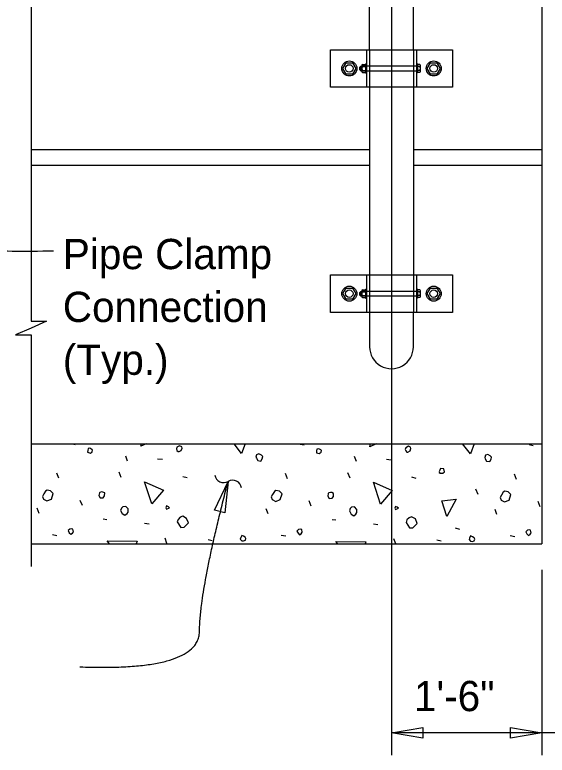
# Model space of a CAD drawing. Extents: x 0 to 41.1, y 0 to 26.4.
# Drawn here: x 23.735 to 27.279, y 12.395 to 17.327 of the extents above; entities that cross this region are included whole.
import ezdxf

# ---------------------------------------------------------------- set-up
doc = ezdxf.new("R2010")
doc.units = 0
for name, color, linetype in [('CL_Major', 7, 'Continuous'), ('Dimension', 7, 'Continuous'), ('Miscellaneous', 7, 'Continuous'), ('SteelMisc', 7, 'Continuous'), ('SteelMisc_h', 7, 'Continuous'), ('SupstrConc', 7, 'Continuous'), ('TextStructures', 7, 'Continuous')]:
    doc.layers.add(name, color=color, linetype=linetype)

msp = doc.modelspace()

# ---------------------------------------------------------------- linework, layer by layer
at = {"layer": 'CL_Major'}
msp.add_line((26.2429, 25.6784), (26.2429, 12.3953), dxfattribs=at)
at = {"layer": 'Dimension'}
for p, q in [((27.2429, 13.6294), (27.2429, 12.3953)), ((28.5763, 12.5434), (26.2429, 12.5434))]:
    msp.add_line(p, q, dxfattribs=at)
for points in [[(23.8431, 20.1983), (23.8431, 19.1806), (23.9465, 19.1806), (23.8431, 19.1356), (23.7398, 19.0906), (23.8431, 19.0906), (23.8431, 17.1361)], [(23.8431, 17.1361), (23.8431, 15.2855), (23.9464, 15.2855), (23.8431, 15.2405), (23.7397, 15.1955), (23.8431, 15.1955), (23.8431, 13.653)]]:
    msp.add_lwpolyline(points, dxfattribs=at)
for points in [[(25.1546, 14.219), (25.1324, 14.009), (25.0644, 14.0281)], [(26.2429, 12.5434), (26.4512, 12.5787), (26.4512, 12.5081)], [(27.2429, 12.5434), (27.0347, 12.5081), (27.0347, 12.5787)]]:
    msp.add_lwpolyline(points, close=True, dxfattribs=at)
for centre, start, end in [((25.1255, 14.2702), 188.4294, 300.1567), ((25.1854, 14.1671), 8.4294, 120.1567)]:
    msp.add_arc(centre, 0.0596, start, end, dxfattribs=at)
for points in [[(23.9932, 15.7529), (23.0399, 15.7236), (23.3618, 16.2556), (23.3935, 16.8155), (23.1813, 16.9916), (22.6122, 16.9694)], [(24.1685, 12.9835), (24.964, 12.9538), (24.9656, 13.4901), (25.1547, 14.2189)]]:
    msp.add_open_spline(points, degree=2, dxfattribs=at)
at = {"layer": 'Miscellaneous'}
for p, q in [((26.0354, 16.9625), (26.0354, 16.9746)), ((26.0411, 16.9625), (26.0411, 16.9746)), ((26.0354, 15.4625), (26.0354, 15.4746)), ((26.0411, 15.4625), (26.0411, 15.4746)), ((24.1186, 14.4695), (24.1373, 14.4657)), ((25.6346, 14.4675), (25.6611, 14.4622)), ((27.1584, 14.4639), (27.185, 14.4586)), ((24.4856, 14.3543), (24.4732, 14.3879)), ((24.6853, 14.3702), (24.7172, 14.3667)), ((26.0094, 14.3508), (25.997, 14.3844)), ((26.2092, 14.3667), (26.241, 14.3632)), ((24.0277, 14.2394), (24.0136, 14.2748)), ((24.4432, 14.2447), (24.429, 14.2801)), ((24.8533, 14.2518), (24.8816, 14.2447)), ((25.5515, 14.2359), (25.5374, 14.2712)), ((25.967, 14.2412), (25.9528, 14.2765)), ((27.0754, 14.2324), (27.0612, 14.2677)), ((26.3771, 14.2483), (26.4054, 14.2412)), ((26.819, 14.1316), (26.8049, 14.1669)), ((24.1851, 14.0573), (24.1709, 14.0927)), ((25.7089, 14.0538), (25.6947, 14.0892)), ((27.2327, 14.0503), (27.2185, 14.0856)), ((23.8969, 14.0061), (23.8845, 14.0397)), ((25.4207, 14.0025), (25.4084, 14.0361)), ((26.9445, 13.999), (26.9322, 14.0326)), ((24.3229, 13.969), (24.3477, 13.9654)), ((25.8468, 13.9654), (25.8715, 13.9619)), ((24.5987, 13.9407), (24.6288, 13.9354)), ((26.1225, 13.9371), (26.1526, 13.9318)), ((26.667, 13.9089), (26.6953, 13.9018)), ((23.9853, 13.8647), (24.0154, 13.8594)), ((25.5091, 13.8611), (25.5392, 13.8558)), ((27.0329, 13.8576), (27.063, 13.8523)), ((24.7472, 13.8063), (24.7348, 13.8399)), ((25.0212, 13.8328), (25.0495, 13.8258)), ((26.271, 13.8028), (26.2587, 13.8364)), ((26.545, 13.8293), (26.5733, 13.8222))]:
    msp.add_line(p, q, dxfattribs=at)
for points in [[(24.574, 14.4533), (24.5789, 14.4695)], [(24.6099, 14.4695), (24.574, 14.4533)], [(24.8215, 14.418), (24.8285, 14.418), (24.8427, 14.425), (24.848, 14.4409), (24.8462, 14.4498), (24.8321, 14.4569), (24.8144, 14.4463), (24.8109, 14.4356), (24.8144, 14.425), (24.8215, 14.418)], [(25.244, 14.4056), (25.1954, 14.4695)], [(25.2678, 14.4695), (25.244, 14.4056)], [(26.0978, 14.4498), (26.1038, 14.4695)], [(26.1416, 14.4695), (26.0978, 14.4498)], [(26.3453, 14.4144), (26.3523, 14.4144), (26.3665, 14.4215), (26.3718, 14.4374), (26.37, 14.4463), (26.3559, 14.4533), (26.3382, 14.4427), (26.3347, 14.4321), (26.3382, 14.4215), (26.3453, 14.4144)], [(26.7678, 14.4021), (26.7165, 14.4695)], [(26.793, 14.4695), (26.7678, 14.4021)], [(24.2186, 14.4127), (24.2381, 14.4074), (24.2505, 14.4162), (24.2522, 14.4286), (24.2487, 14.4321), (24.2346, 14.4392), (24.2222, 14.4374), (24.2204, 14.425), (24.2186, 14.4127)], [(25.3429, 14.3738), (25.3518, 14.3579), (25.373, 14.3543), (25.3818, 14.3702), (25.3854, 14.3844), (25.3765, 14.3932), (25.3606, 14.4021), (25.3447, 14.3968), (25.3394, 14.3808), (25.3429, 14.3738)], [(25.7425, 14.4091), (25.7619, 14.4038), (25.7743, 14.4127), (25.7761, 14.425), (25.7725, 14.4286), (25.7584, 14.4356), (25.746, 14.4339), (25.7442, 14.4215), (25.7425, 14.4091)], [(26.8668, 14.3702), (26.8756, 14.3543), (26.8968, 14.3508), (26.9057, 14.3667), (26.9092, 14.3808), (26.9004, 14.3897), (26.8844, 14.3985), (26.8685, 14.3932), (26.8632, 14.3773), (26.8668, 14.3702)], [(26.5645, 14.273), (26.5857, 14.273), (26.5963, 14.2836), (26.591, 14.3031), (26.568, 14.3048), (26.5645, 14.2942), (26.5592, 14.2854), (26.5645, 14.273), (26.5609, 14.2765)], [(24.6464, 14.0697), (24.5987, 14.2164), (24.7242, 14.1616), (24.6464, 14.0697)], [(26.1703, 14.0662), (26.1225, 14.2129), (26.248, 14.1581), (26.1703, 14.0662)], [(23.9252, 14.1015), (23.9482, 14.0892), (23.9782, 14.1015), (23.9906, 14.1387), (23.9729, 14.1563), (23.9499, 14.1616), (23.9393, 14.1546), (23.927, 14.1351), (23.9181, 14.1192), (23.9252, 14.1015)], [(25.449, 14.098), (25.472, 14.0856), (25.502, 14.098), (25.5144, 14.1351), (25.4967, 14.1528), (25.4738, 14.1581), (25.4632, 14.151), (25.4508, 14.1316), (25.4419, 14.1157), (25.449, 14.098)], [(26.9728, 14.0945), (26.9958, 14.0821), (27.0259, 14.0945), (27.0382, 14.1316), (27.0206, 14.1493), (26.9976, 14.1546), (26.987, 14.1475), (26.9746, 14.1281), (26.9658, 14.1121), (26.9728, 14.0945)], [(24.2947, 14.1245), (24.3035, 14.1086), (24.3229, 14.1104), (24.3318, 14.1228), (24.3336, 14.1422), (24.3212, 14.1475), (24.3123, 14.1493), (24.3017, 14.1457), (24.2982, 14.1422), (24.2947, 14.1245)], [(25.8185, 14.121), (25.8273, 14.1051), (25.8468, 14.1068), (25.8556, 14.1192), (25.8574, 14.1387), (25.845, 14.144), (25.8362, 14.1457), (25.8255, 14.1422), (25.822, 14.1387), (25.8185, 14.121)], [(24.7454, 14.0344), (24.7649, 14.0432), (24.7578, 14.0503), (24.7454, 14.0556), (24.7401, 14.0432), (24.7454, 14.0344)], [(26.6122, 13.9849), (26.5786, 14.0892), (26.6723, 14.1015), (26.6122, 13.9849)], [(24.4396, 14.0255), (24.4502, 14.0043), (24.4679, 13.9937), (24.482, 14.0043), (24.4891, 14.0149), (24.4891, 14.0361), (24.4732, 14.052), (24.4538, 14.0503), (24.4449, 14.0414), (24.4396, 14.0255)], [(25.9634, 14.022), (25.974, 14.0008), (25.9917, 13.9902), (26.0059, 14.0008), (26.0129, 14.0114), (26.0129, 14.0326), (25.997, 14.0485), (25.9776, 14.0467), (25.9687, 14.0379), (25.9634, 14.022)], [(26.2693, 14.0308), (26.2887, 14.0397), (26.2816, 14.0467), (26.2693, 14.052), (26.264, 14.0397), (26.2693, 14.0308)], [(24.8162, 13.9495), (24.8391, 13.9124), (24.8621, 13.9142), (24.871, 13.923), (24.8904, 13.9424), (24.878, 13.9725), (24.8533, 13.9866), (24.8356, 13.9796), (24.8215, 13.9654), (24.8162, 13.9495)], [(26.34, 13.946), (26.3629, 13.9089), (26.3859, 13.9106), (26.3948, 13.9195), (26.4142, 13.9389), (26.4018, 13.969), (26.3771, 13.9831), (26.3594, 13.976), (26.3453, 13.9619), (26.34, 13.946)], [(24.0967, 13.877), (24.1073, 13.8664), (24.1179, 13.8735), (24.125, 13.8841), (24.1214, 13.9018), (24.1126, 13.9035), (24.1002, 13.9018), (24.0896, 13.8912), (24.0967, 13.877)], [(25.2457, 13.824), (25.2581, 13.8222), (25.2705, 13.8275), (25.274, 13.8381), (25.2687, 13.847), (25.2581, 13.8541), (25.2457, 13.8594), (25.2386, 13.8452), (25.2351, 13.8346), (25.2457, 13.824)], [(25.6205, 13.8735), (25.6311, 13.8629), (25.6417, 13.87), (25.6488, 13.8806), (25.6452, 13.8982), (25.6364, 13.9), (25.624, 13.8982), (25.6134, 13.8876), (25.6205, 13.8735)], [(27.1443, 13.87), (27.1549, 13.8594), (27.1655, 13.8664), (27.1726, 13.877), (27.1691, 13.8947), (27.1602, 13.8965), (27.1478, 13.8947), (27.1372, 13.8841), (27.1443, 13.87)], [(24.3642, 13.8028), (24.3495, 13.8222), (24.5492, 13.8205), (24.5426, 13.8028)], [(25.8854, 13.8028), (25.8733, 13.8187), (26.073, 13.8169), (26.0678, 13.8028)], [(26.7695, 13.8205), (26.7819, 13.8187), (26.7943, 13.824), (26.7978, 13.8346), (26.7925, 13.8434), (26.7819, 13.8505), (26.7695, 13.8558), (26.7625, 13.8417), (26.7589, 13.8311), (26.7695, 13.8205)]]:
    msp.add_lwpolyline(points, dxfattribs=at)
at = {"layer": 'SteelMisc'}
for p, q in [((26.0971, 17.0944), (26.0971, 17.6079)), ((26.3888, 17.0944), (26.3888, 17.6079)), ((25.837, 17.0944), (26.6489, 17.0944)), ((25.837, 16.8444), (25.837, 17.0944)), ((26.0763, 17.0944), (26.0763, 16.8444)), ((26.4096, 17.0944), (26.4096, 16.8444)), ((26.6489, 17.0944), (26.6489, 16.8444)), ((26.0326, 16.9774), (26.0382, 16.984)), ((26.0326, 16.9597), (26.0326, 16.9774)), ((26.0382, 16.984), (26.0447, 16.984)), ((26.0382, 16.9541), (26.0382, 16.984)), ((26.0447, 16.9873), (26.0447, 16.9516)), ((26.0494, 16.9824), (26.0697, 16.9824)), ((26.0496, 16.9954), (26.0697, 16.9954)), ((26.0697, 16.9997), (26.0697, 16.9391)), ((26.0697, 16.9997), (26.0763, 16.9997)), ((26.0697, 16.9954), (26.0697, 16.9435)), ((26.4159, 16.9997), (26.4098, 16.9997)), ((26.4159, 16.9997), (26.4159, 16.9391)), ((26.4306, 16.9954), (26.4159, 16.9954)), ((26.4307, 16.9824), (26.4159, 16.9824)), ((26.4357, 16.95), (26.4357, 16.9889)), ((26.0326, 16.9597), (26.0382, 16.9541)), ((26.0382, 16.9541), (26.0447, 16.9541)), ((26.0494, 16.9565), (26.0697, 16.9565)), ((26.0497, 16.9435), (26.0697, 16.9435)), ((26.0697, 16.9391), (26.0763, 16.9391)), ((26.4159, 16.9391), (26.4098, 16.9391)), ((26.4307, 16.9564), (26.4159, 16.9564)), ((26.4306, 16.9434), (26.4159, 16.9434)), ((26.6489, 16.8444), (25.837, 16.8444)), ((26.0971, 16.8444), (26.0971, 15.5944)), ((26.3888, 16.8444), (26.3888, 15.5944)), ((25.837, 15.5944), (26.6489, 15.5944)), ((25.837, 15.3444), (25.837, 15.5944)), ((26.0763, 15.5944), (26.0763, 15.3444)), ((26.4096, 15.5944), (26.4096, 15.3444)), ((26.6489, 15.5944), (26.6489, 15.3444)), ((26.0447, 15.4873), (26.0447, 15.4516)), ((26.0496, 15.4954), (26.0697, 15.4954)), ((26.0697, 15.4997), (26.0697, 15.4391)), ((26.0697, 15.4997), (26.0763, 15.4997)), ((26.0697, 15.4954), (26.0697, 15.4435)), ((26.4159, 15.4997), (26.4098, 15.4997)), ((26.4159, 15.4997), (26.4159, 15.4391)), ((26.4306, 15.4954), (26.4159, 15.4954)), ((26.4357, 15.45), (26.4357, 15.4889)), ((26.0326, 15.4774), (26.0382, 15.484)), ((26.0326, 15.4597), (26.0326, 15.4774)), ((26.0326, 15.4597), (26.0382, 15.4541)), ((26.0382, 15.484), (26.0447, 15.484)), ((26.0382, 15.4541), (26.0382, 15.484)), ((26.0382, 15.4541), (26.0447, 15.4541)), ((26.0494, 15.4824), (26.0697, 15.4824)), ((26.0494, 15.4565), (26.0697, 15.4565)), ((26.0497, 15.4435), (26.0697, 15.4435)), ((26.0697, 15.4391), (26.0763, 15.4391)), ((26.4159, 15.4391), (26.4098, 15.4391)), ((26.4307, 15.4824), (26.4159, 15.4824)), ((26.4307, 15.4564), (26.4159, 15.4564)), ((26.4306, 15.4434), (26.4159, 15.4434)), ((26.6489, 15.3444), (25.837, 15.3444)), ((26.097, 15.3444), (26.097, 15.1153)), ((26.3887, 15.1153), (26.3887, 15.3444))]:
    msp.add_line(p, q, dxfattribs=at)
for points in [[(25.9403, 17.007), (25.9836, 17.007), (26.0053, 16.9694), (25.9836, 16.9319), (25.9403, 16.9319), (25.9186, 16.9694)], [(26.5023, 17.007), (26.5456, 17.007), (26.5673, 16.9694), (26.5456, 16.9319), (26.5023, 16.9319), (26.4806, 16.9694)], [(25.9403, 15.507), (25.9836, 15.507), (26.0053, 15.4694), (25.9836, 15.4319), (25.9403, 15.4319), (25.9186, 15.4694)], [(26.5023, 15.507), (26.5456, 15.507), (26.5673, 15.4694), (26.5456, 15.4319), (26.5023, 15.4319), (26.4806, 15.4694)]]:
    msp.add_lwpolyline(points, close=True, dxfattribs=at)
for centre, radius in [((25.962, 16.9694), 0.05), ((26.5239, 16.9694), 0.05), ((25.962, 16.9694), 0.025), ((26.5239, 16.9694), 0.025), ((25.962, 15.4694), 0.05), ((25.962, 15.4694), 0.025), ((26.5239, 15.4694), 0.05), ((26.5239, 15.4694), 0.025)]:
    msp.add_circle(centre, radius, dxfattribs=at)
for centre, radius, start, end in [((26.0513, 16.9889), 0.00674, 104.4891, 254.1889), ((26.0642, 16.9694), 0.0196, 138.628, 221.372), ((26.4289, 16.9889), 0.00673, 285.7823, 75.5404), ((26.416, 16.9694), 0.0196, 318.628, 41.372), ((26.0513, 16.95), 0.00673, 105.7823, 255.5404), ((26.4289, 16.95), 0.00674, 284.4891, 74.1889), ((26.0513, 15.4889), 0.00674, 104.4891, 254.1889), ((26.4289, 15.4889), 0.00673, 285.7823, 75.5404), ((26.0642, 15.4694), 0.0196, 138.628, 221.372), ((26.0513, 15.45), 0.00673, 105.7823, 255.5404), ((26.4289, 15.45), 0.00674, 284.4891, 74.1889), ((26.416, 15.4694), 0.0196, 318.628, 41.372)]:
    msp.add_arc(centre, radius, start, end, dxfattribs=at)
msp.add_ellipse((26.2429, 15.1153), major_axis=(0, 0.1458), ratio=0.999499, start_param=1.570796, end_param=4.712389, dxfattribs=at)
at = {"layer": 'SteelMisc_h'}
for p, q in [((26.0971, 17.0944), (26.0971, 16.8444)), ((26.3888, 17.0944), (26.3888, 16.8444)), ((26.4096, 16.984), (26.0447, 16.984)), ((26.0447, 16.9541), (26.4096, 16.9541)), ((26.0971, 15.5944), (26.0971, 15.3444)), ((26.3888, 15.5944), (26.3888, 15.3444)), ((26.4096, 15.484), (26.0447, 15.484)), ((26.0447, 15.4541), (26.4096, 15.4541))]:
    msp.add_line(p, q, dxfattribs=at)
at = {"layer": 'SupstrConc'}
for p, q in [((27.2429, 17.4693), (27.2429, 13.8028)), ((23.8431, 16.4295), (26.0971, 16.4295)), ((26.3888, 16.4295), (27.2428, 16.4295)), ((23.8431, 16.3254), (26.0971, 16.3254)), ((26.3888, 16.3254), (27.2428, 16.3254)), ((23.8431, 14.4695), (27.2429, 14.4695)), ((23.8431, 13.8028), (27.2429, 13.8028))]:
    msp.add_line(p, q, dxfattribs=at)

# ---------------------------------------------------------------- texts
at = {"layer": 'Dimension'}
for s, p in [('Pipe Clamp ', (24.0545, 15.6326)), ('Connection ', (24.0545, 15.2806)), ('(Typ.)', (24.0545, 14.9286))]:
    msp.add_text(s, height=0.2016, dxfattribs=at).set_placement(p)
at = {"layer": 'TextStructures'}
msp.add_text('1\'-6"', height=0.2016, dxfattribs=at).set_placement((26.3923, 12.6886))

doc.saveas('drawing.dxf')
